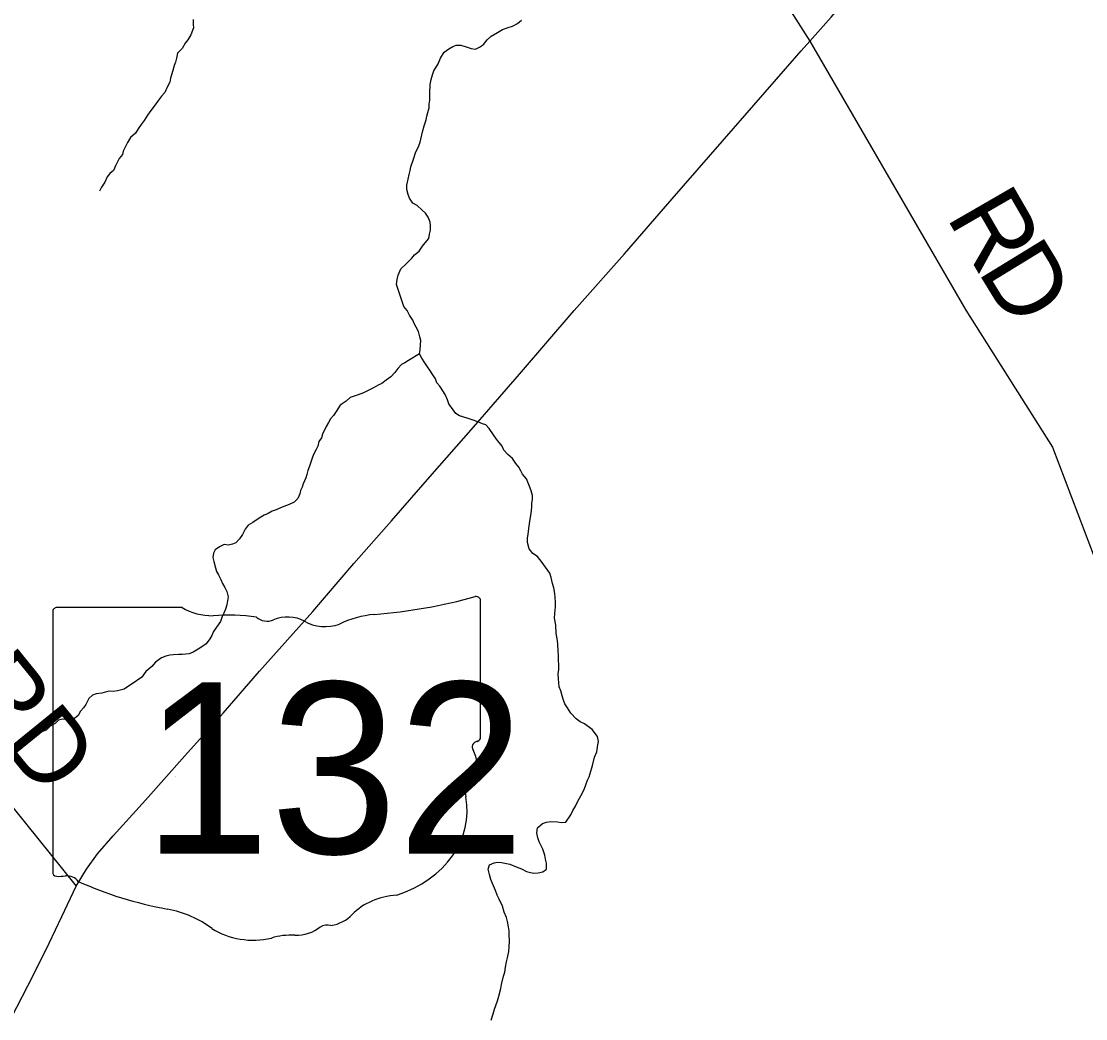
# Model space of a CAD drawing. Extents: x 1310247 to 1664935, y 284496 to 704931.
# Drawn here: x 1512676 to 1517006, y 471214 to 475269 of the extents above; entities that cross this region are included whole.
import ezdxf

# ---------------------------------------------------------------- set-up
doc = ezdxf.new("R2010")
doc.units = 0
for name, color, linetype in [('GM_X_Airport_Class_2', 7, 'Continuous'), ('GM_X_County_Road_Text', 7, 'Continuous'), ('GM_X_County_Subdivision_Text', 7, 'Continuous'), ('GM_X_Interstate_Shield', 7, 'Continuous'), ('GM_X_Minor_River_Text', 7, 'Continuous'), ('GM_X_Township_Road', 7, 'Continuous'), ('GM_X_Township_Subdivision', 7, 'Continuous'), ('GM_X_Unincorporated_Location', 7, 'Continuous')]:
    doc.layers.add(name, color=color, linetype=linetype)

msp = doc.modelspace()

# ---------------------------------------------------------------- linework, layer by layer
at = {"layer": 'GM_X_Airport_Class_2'}
for p, q in [((1514544.4, 472359.9), (1514544.4, 472912.6)), ((1512804.2, 472868.2), (1512804.2, 471811.6)), ((1513331, 472886.4), (1512821.4, 472886.4)), ((1514544.3, 472360), (1514544.4, 472359.9))]:
    msp.add_line(p, q, dxfattribs=at)
for centre, major_axis, start_param, end_param in [((1513924.5, 474327), (1845.5, 0), 4.814394, 5.042369), ((1514525.1, 472914.9), (19.4, 0), 6.141152, 7.989035), ((1512824.2, 472870.5), (20.2, 0), 1.712693, 3.28349), ((1513452.3, 473009.1), (195.5, 0), 4.042523, 4.731795), ((1513517.2, 472293.2), (702, 0), 1.404758, 1.657858), ((1513676.6, 472876), (56.4, 0), 3.836095, 5.185415), ((1513759.4, 472753.8), (117.3, 0), 0.950623, 2.079405), ((1513910.7, 472921.3), (141.1, 0), 4.081561, 5.145723), ((1514159.9, 472563.7), (371.3, 0), 1.699011, 2.107814), ((1514539.9, 472319.3), (30, 0), 1.883978, 3.671073), ((1514523.8, 472357.7), (20.7, 0), 5.05454, 6.418171), ((1514349.2, 472249.4), (180, 0), 5.934695, 6.695948), ((1514613.8, 472128.6), (130.9, 0), 2.387724, 3.262537), ((1514027.9, 472058.2), (461.6, 0), 5.101752, 6.440018), ((1512824.3, 471809.3), (20.3, 0), 3.00124, 4.508301), ((1512827.4, 471917.4), (155.2, 0), 4.665946, 4.897461), ((1512859.2, 471750.6), (56, 0), 0.519207, 1.627899), ((1513565.8, 472700), (1332.7, 0), 4.195997, 4.488961), ((1514222.5, 471515), (252.8, 0), 1.647645, 2.488434), ((1513168.5, 471336.9), (417, 0), 0.823519, 1.323587), ((1513902.2, 471709.2), (149.1, 0), 4.937069, 5.64225), ((1513619.4, 471745.4), (264.6, 0), 4.026481, 4.996735), ((1513791.6, 471666.3), (141, 0), 4.691044, 5.507374), ((1513919.2, 471563.9), (39.7, 0), 1.147584, 2.315152), ((1513772.3, 471380.1), (217.4, 0), 1.495662, 1.94098)]:
    msp.add_ellipse(centre, major_axis=major_axis, ratio=0.8, start_param=start_param, end_param=end_param, dxfattribs=at)
at = {"layer": 'GM_X_County_Road_Text'}
msp.add_lwpolyline([(1512412.2, 479868.3), (1512884, 479728.6), (1513011.2, 479638.4), (1513334, 479148.4), (1513670.6, 478637.4), (1514118, 477962.6), (1514571.2, 477265.7), (1514855.2, 476804), (1515883.3, 475188.3), (1516518, 474094.8), (1516870.8, 473537.8), (1517050.2, 473063.7), (1517450.2, 471932.4), (1517635.9, 471351.9), (1517767.3, 471027)], dxfattribs=at)
at = {"layer": 'GM_X_County_Subdivision_Text'}
msp.add_lwpolyline([(1509251.1, 476281.3), (1510461, 474407.4), (1510561.7, 474297.5), (1510963.8, 474062.6), (1511162.2, 473909.2), (1511331.7, 473699.9), (1512899.4, 471753.3)], dxfattribs=at)
at = {"layer": 'GM_X_Interstate_Shield'}
for points in [[(1515848.5, 475149.2), (1515883.3, 475188.3), (1515970.2, 475286.1), (1516157.6, 475503.6), (1516344.9, 475717.1), (1516502.5, 475903.6)], [(1512634.5, 471216.7), (1512726.1, 471392.8), (1512790.2, 471521.5), (1512841.6, 471630.4), (1512899.4, 471753.3), (1512941.7, 471822.4), (1512985.8, 471885.3), (1513050.3, 471957.8), (1513181.2, 472102.6), (1513341.4, 472282.8), (1513497.4, 472457.1), (1513645.3, 472627.5), (1513861.6, 472870.4), (1514028.2, 473064.4), (1514182.2, 473238.7), (1514338.3, 473417), (1514515.2, 473618.7), (1514702.6, 473834.3), (1514925.4, 474093), (1515129.3, 474324.1), (1515323, 474547.5), (1515572.7, 474833.6), (1515830.8, 475129.4), (1515848.5, 475149.2)]]:
    msp.add_lwpolyline(points, dxfattribs=at)
at = {"layer": 'GM_X_Minor_River_Text'}
for points in [[(1513375.4, 475276.3), (1513374.9, 475256.3), (1513376.6, 475242.2), (1513365.8, 475214.4), (1513353.3, 475194.6), (1513342.9, 475180.8), (1513330.3, 475159.1), (1513311.7, 475139.5), (1513307.2, 475119.5), (1513302.8, 475103.5), (1513298.4, 475089.6), (1513291.9, 475069.7), (1513287.4, 475051.8), (1513283.1, 475037.8), (1513280.7, 475021.8), (1513270.1, 475002), (1513259.5, 474980.2), (1513247.1, 474964.4), (1513234.6, 474948.7), (1513216, 474925), (1513203.5, 474907.3), (1513188.9, 474887.6), (1513176.3, 474865.8), (1513163.9, 474850.1), (1513151.4, 474832.3), (1513140.9, 474814.5), (1513120.4, 474796.9), (1513107.8, 474777.2), (1513099.3, 474757.3), (1513090.9, 474741.5), (1513088.5, 474727.5), (1513074, 474711.8), (1513059.2, 474682), (1513050.7, 474662.2), (1513036.4, 474650.5), (1513026, 474636.7), (1513015.4, 474614.9), (1513002.8, 474595.1), (1512994.4, 474579.3)], [(1514396.6, 475143.4), (1514415, 475157), (1514431.3, 475166.6), (1514445.5, 475172.3), (1514463.6, 475171.9), (1514485.5, 475165.3), (1514505.5, 475158.8), (1514523.5, 475156.4), (1514539.7, 475164), (1514556.1, 475175.7), (1514570.6, 475193.4), (1514587.1, 475209), (1514613.6, 475224.4), (1514634, 475236), (1514656.2, 475243.5), (1514674.5, 475249.1), (1514694.8, 475260.6), (1514711.2, 475274.2)], [(1514754.9, 473324.9), (1514755.3, 473340.9), (1514749.8, 473361.1), (1514744.1, 473375.3), (1514736.6, 473395.6), (1514730.9, 473409.7), (1514715.3, 473428.2), (1514707.6, 473442.4), (1514700, 473456.6), (1514688.3, 473471), (1514674.7, 473491.4), (1514655.1, 473507.9), (1514639.4, 473526.3), (1514631.8, 473542.6), (1514608.4, 473571.2), (1514596.8, 473587.5), (1514579.4, 473614), (1514565.7, 473628.4), (1514551.7, 473632.8), (1514533.8, 473641.2), (1514513.9, 473647.7), (1514490, 473656.3), (1514458.1, 473665.1), (1514444.3, 473675.5), (1514432.6, 473689.8), (1514415.1, 473714.3), (1514409.5, 473730.5), (1514400, 473752.8), (1514390.3, 473767.1), (1514378.7, 473785.4), (1514367, 473799.8), (1514361.4, 473815.9), (1514347.9, 473836.3), (1514338.2, 473850.6), (1514328.5, 473864.9), (1514316.9, 473881.2), (1514305.3, 473899.6), (1514295.7, 473917.8), (1514298.1, 473933.8), (1514300.6, 473953.8), (1514301, 473971.9), (1514297.4, 473986), (1514291.9, 474008.2), (1514282.3, 474026.5), (1514274.6, 474040.8), (1514269, 474054.9), (1514255.4, 474075.3), (1514245.8, 474093.6), (1514232.2, 474110), (1514226.6, 474126.2), (1514215.3, 474158.6), (1514207.9, 474182.8), (1514202.3, 474199), (1514204.8, 474219), (1514209.2, 474237), (1514219.9, 474262.8), (1514240.5, 474282.4), (1514265.2, 474305.8), (1514275.6, 474319.6), (1514294.1, 474335.2), (1514308.6, 474355), (1514319, 474368.7), (1514333.5, 474386.5), (1514336, 474404.5), (1514340.4, 474420.4), (1514340.8, 474438.4), (1514339.2, 474452.5), (1514331.6, 474472.8), (1514320, 474489.1), (1514306.2, 474501.5), (1514286.6, 474520), (1514268.8, 474530.5), (1514255.2, 474550.9), (1514249.6, 474565), (1514244, 474585.2), (1514244.5, 474603.3), (1514249.1, 474627.3), (1514253.6, 474647.2), (1514258, 474663.2), (1514260.4, 474677.1), (1514271.2, 474709), (1514279.9, 474734.9), (1514292.7, 474762.7), (1514299.1, 474778.5), (1514308.2, 474820.5), (1514314.8, 474844.4), (1514323.4, 474868.2), (1514325.9, 474884.2), (1514330.2, 474898.2), (1514334.7, 474918.1), (1514335.1, 474932.2), (1514337.5, 474948.2), (1514337.8, 474962.2), (1514338.2, 474978.3), (1514339.1, 475012.3), (1514343.6, 475032.3), (1514348.1, 475052.2), (1514354.5, 475068.2), (1514371.3, 475095.8), (1514381.9, 475119.7), (1514396.6, 475143.4)], [(1514295.7, 473917.8), (1514250.8, 473890.8), (1514236.5, 473881.1), (1514222.2, 473873.5), (1514207.8, 473857.8), (1514195.3, 473842), (1514178.8, 473824.3), (1514160.4, 473810.8), (1514142, 473797.1), (1514127.7, 473789.5), (1514109.4, 473779.9), (1514087, 473768.4), (1514068.7, 473758.8), (1514046.4, 473751.3), (1514014, 473740), (1513997.5, 473724.4), (1513973.1, 473708.9), (1513956.3, 473683.2), (1513945.9, 473667.4), (1513933.5, 473653.7), (1513925.1, 473637.8), (1513916.6, 473622), (1513901.8, 473590.3), (1513897.4, 473576.3), (1513887, 473560.5), (1513882.5, 473542.6), (1513876.1, 473528.7), (1513865.6, 473510.9), (1513861.3, 473496.9), (1513854.9, 473481), (1513848.3, 473461.1), (1513841.9, 473443.2), (1513837.4, 473427.3), (1513833.1, 473413.3), (1513822.4, 473389.5), (1513818.1, 473375.6), (1513811.7, 473361.7), (1513809.3, 473347.7), (1513800.8, 473329.8), (1513786.4, 473314.1), (1513766.1, 473304.6), (1513743.8, 473297.1), (1513727.5, 473289.5), (1513713.3, 473283.8), (1513697.1, 473278.2), (1513680.8, 473268.5), (1513664.5, 473260.9), (1513650.3, 473253.2), (1513631.9, 473241.6), (1513617.6, 473231.9), (1513599.2, 473220.3), (1513586.8, 473204.6), (1513576.2, 473182.8), (1513563.7, 473165), (1513549.2, 473149.3), (1513535, 473143.6), (1513518.9, 473140), (1513500.9, 473142.4), (1513482.5, 473132.8), (1513464.2, 473121.2), (1513457.8, 473107.4), (1513455.3, 473089.4), (1513459, 473073.2), (1513466.3, 473047), (1513470, 473032.8), (1513477.7, 473018.6), (1513487.3, 473000.3), (1513494.9, 472984.1), (1513504.5, 472967.8), (1513512.2, 472951.5), (1513517.6, 472929.3), (1513515.2, 472913.4), (1513512.8, 472897.4), (1513506.3, 472879.5), (1513499.9, 472863.6), (1513493.5, 472849.7), (1513487, 472829.8), (1513470.3, 472806.1), (1513457.8, 472788.3), (1513451.4, 472772.4), (1513443, 472758.6), (1513428.5, 472738.9), (1513401.9, 472721.5), (1513375.4, 472704), (1513359.2, 472698.4), (1513345.1, 472696.8), (1513331, 472695.1), (1513316.9, 472695.4), (1513294.8, 472694), (1513280.7, 472692.3), (1513264.5, 472688.7), (1513246.2, 472681.1), (1513221.7, 472663.6), (1513207.2, 472645.9), (1513182.6, 472626.4), (1513165.9, 472602.8), (1513127.1, 472575.6), (1513108.7, 472564), (1513094.4, 472554.3), (1513068.1, 472546.9), (1513050, 472545.3)], [(1514640.7, 471648.2), (1514633.2, 471672.5), (1514619.9, 471700.9), (1514612.3, 471717.1), (1514604.7, 471735.4), (1514593.3, 471763.7), (1514585.7, 471780), (1514580.2, 471800.2), (1514574.7, 471822.4), (1514581.2, 471840.3), (1514599.5, 471847.9), (1514613.6, 471851.5), (1514629.6, 471849.1), (1514663.6, 471842.3), (1514689.4, 471831.6), (1514711.3, 471823.1), (1514731.2, 471812.6), (1514747.1, 471808.2), (1514761.1, 471805.8), (1514779.2, 471807.4), (1514797.4, 471811), (1514811.8, 471822.7), (1514812.4, 471846.7), (1514808.8, 471862.9), (1514805.1, 471879), (1514797.7, 471903.3), (1514782.4, 471933.7), (1514776.8, 471949.9), (1514773.3, 471970.1), (1514775.8, 471990.1), (1514796.3, 472007.6), (1514812.5, 472013.3), (1514830.7, 472016.8), (1514856.7, 472014.2), (1514872.7, 472011.8), (1514890.9, 472013.4), (1514911.7, 472043), (1514920.2, 472060.8), (1514930.7, 472078.6), (1514939.2, 472098.5), (1514958.1, 472130.2), (1514966.6, 472150), (1514973, 472165.9), (1514979.5, 472183.8), (1514985.9, 472197.7), (1514990.2, 472211.6), (1514999.1, 472243.5), (1515008, 472277.4), (1515016.5, 472299.3), (1515021.3, 472327.3), (1515023.6, 472341.3), (1515020.1, 472361.4), (1514998.7, 472390), (1514967.2, 472412.8), (1514949.3, 472421.3), (1514933.5, 472433.7), (1514912, 472456.3), (1514898.5, 472478.7), (1514886.8, 472495), (1514881.2, 472509.2), (1514875.6, 472527.4), (1514870.1, 472547.6), (1514864.5, 472563.8), (1514861.3, 472596), (1514859.7, 472616.1), (1514862.2, 472634.1), (1514862.6, 472650.1), (1514861.2, 472674.2), (1514861.6, 472690.3), (1514860, 472708.4), (1514858.7, 472736.5), (1514857.1, 472752.6), (1514851.8, 472780.8), (1514850.7, 472815), (1514845.3, 472843.2), (1514845.8, 472861.2), (1514848.2, 472875.2), (1514848.5, 472889.2), (1514849, 472907.3), (1514847.4, 472927.4), (1514845.8, 472943.5), (1514842.4, 472965.6), (1514836.8, 472983.8), (1514831.4, 473008), (1514825.8, 473026.2), (1514808.3, 473050.7), (1514794.7, 473069.1), (1514775.3, 473093.7), (1514757.5, 473106.1), (1514741.9, 473124.6), (1514734.5, 473150.8), (1514735, 473168.9), (1514737.3, 473182.9), (1514739.7, 473196.8), (1514742.2, 473216.8), (1514744.7, 473236.9), (1514749.3, 473260.8), (1514751.8, 473280.8), (1514752.2, 473294.9), (1514752.6, 473310.9), (1514754.9, 473324.9)], [(1513050, 472545.3), (1513031.9, 472545.8), (1513003.6, 472538.4), (1512981.4, 472535), (1512965.2, 472529.3), (1512950.8, 472515.6), (1512938.2, 472491.9), (1512929.8, 472478), (1512917.4, 472464.3), (1512906.9, 472446.5), (1512892.5, 472434.8), (1512876.4, 472431.2), (1512860.3, 472431.5), (1512844.3, 472431.9), (1512828.1, 472428.3), (1512813.7, 472414.6), (1512793.3, 472403.1), (1512776.9, 472387.4), (1512762.7, 472381.7), (1512748.4, 472376), (1512734.3, 472372.4), (1512714.1, 472366.8), (1512697.9, 472363.2), (1512681.5, 472351.6), (1512673, 472331.7)], [(1514587.5, 471208.1), (1514596.1, 471234), (1514600.7, 471253.9), (1514613.6, 471287.7), (1514618, 471305.7), (1514626.9, 471337.6), (1514629.3, 471353.5), (1514638.1, 471387.5), (1514642.6, 471403.4), (1514645.1, 471423.4), (1514649.6, 471445.3), (1514654.1, 471461.3), (1514658.7, 471487.3), (1514661.2, 471507.3), (1514661.8, 471529.3), (1514660.4, 471555.5), (1514660.8, 471571.5), (1514657.2, 471587.6), (1514653.8, 471609.8), (1514650.2, 471625.9), (1514640.7, 471648.2)]]:
    msp.add_lwpolyline(points, dxfattribs=at)

# ---------------------------------------------------------------- texts
at = {"layer": 'GM_X_Airport_Class_2'}
msp.add_text('132', height=696.1, dxfattribs=at).set_placement((1513171.1, 471886.1))
at = {"layer": 'GM_X_Township_Road'}
for s, rotation, p in [('R', 299.9952, (1516435.8, 474476.2)), ('D', 301.4845, (1516563.2, 474255.6))]:
    msp.add_text(s, height=300, rotation=rotation, dxfattribs=at).set_placement(p)
at = {"layer": 'GM_X_Township_Subdivision'}
msp.add_text('RD', height=300, rotation=309.0466, dxfattribs=at).set_placement((1512407.8, 472555.7))
at = {"layer": 'GM_X_Unincorporated_Location'}
for s in ['s', 'r']:
    msp.add_text(s, height=1, dxfattribs=at).set_placement((1513654.8, 472269.7))
msp.add_text('132', height=1, rotation=0, dxfattribs=at).set_placement((1513301.7, 472196.9))

doc.saveas('drawing.dxf')
